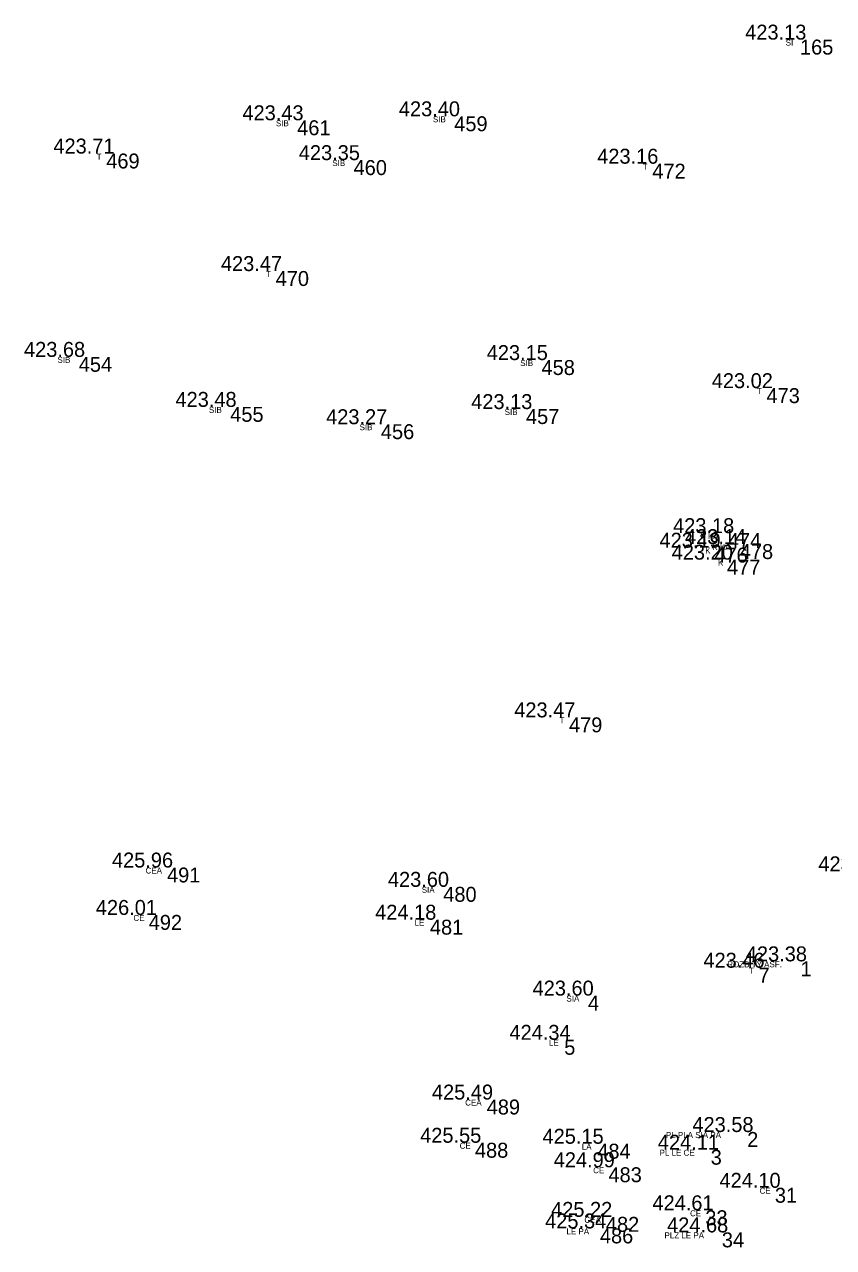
# Model space of a CAD drawing. Extents: x -639373 to -639057, y -1138651 to -1138359.
# Drawn here: x -639183 to -639142.4, y -1138650.6 to -1138589.2 of the extents above; entities that cross this region are included whole.
import ezdxf

# ---------------------------------------------------------------- set-up
doc = ezdxf.new("R2010")
doc.units = 0
for name, color, linetype in [('Vrstva 11', 7, 'Continuous'), ('Vrstva 12', 7, 'Continuous'), ('Vrstva 13', 7, 'Continuous'), ('Vrstva 14', 7, 'Continuous'), ('Vrstva 57', 7, 'Continuous')]:
    doc.layers.add(name, color=color, linetype=linetype)

msp = doc.modelspace()

# ---------------------------------------------------------------- linework, layer by layer
at = {"layer": 'Vrstva 11'}
for p, q in [((-639144.39, -1138589.97), (-639144.39, -1138589.97)), ((-639169.62, -1138594.02), (-639169.62, -1138594.02)), ((-639161.74, -1138593.82), (-639161.74, -1138593.82)), ((-639179.2, -1138595.69), (-639179.2, -1138595.69)), ((-639166.79, -1138596.02), (-639166.79, -1138596.02)), ((-639151.8, -1138596.2), (-639151.8, -1138596.2)), ((-639170.7, -1138601.59), (-639170.7, -1138601.59)), ((-639180.58, -1138605.9), (-639180.58, -1138605.9)), ((-639157.36, -1138606.06), (-639157.36, -1138606.06)), ((-639146.07, -1138607.47), (-639146.07, -1138607.47)), ((-639172.98, -1138608.41), (-639172.98, -1138608.41)), ((-639158.14, -1138608.52), (-639158.14, -1138608.52)), ((-639165.42, -1138609.28), (-639165.42, -1138609.28)), ((-639148.01, -1138614.75), (-639148.01, -1138614.75)), ((-639148.69, -1138615.48), (-639148.69, -1138615.48)), ((-639147.41, -1138615.3), (-639147.41, -1138615.3)), ((-639148.05, -1138616.08), (-639148.05, -1138616.08)), ((-639155.98, -1138624), (-639155.98, -1138624)), ((-639176.15, -1138631.54), (-639176.15, -1138631.54)), ((-639162.29, -1138632.51), (-639162.29, -1138632.51)), ((-639177.07, -1138633.92), (-639177.07, -1138633.92)), ((-639162.96, -1138634.16), (-639162.96, -1138634.16)), ((-639146.47, -1138636.57), (-639146.47, -1138636.57)), ((-639144.36, -1138636.25), (-639144.36, -1138636.25)), ((-639155.03, -1138637.97), (-639155.03, -1138637.97)), ((-639156.22, -1138640.19), (-639156.22, -1138640.19)), ((-639160.11, -1138643.19), (-639160.11, -1138643.19)), ((-639147.04, -1138644.82), (-639147.04, -1138644.82)), ((-639160.7, -1138645.36), (-639160.7, -1138645.36)), ((-639154.56, -1138645.41), (-639154.56, -1138645.41)), ((-639148.87, -1138645.71), (-639148.87, -1138645.71)), ((-639154, -1138646.59), (-639154, -1138646.59)), ((-639145.65, -1138647.62), (-639145.65, -1138647.62)), ((-639149.14, -1138648.75), (-639149.14, -1138648.75)), ((-639154.13, -1138649.08), (-639154.13, -1138649.08)), ((-639154.43, -1138649.66), (-639154.43, -1138649.66)), ((-639148.31, -1138649.86), (-639148.31, -1138649.86))]:
    msp.add_line(p, q, dxfattribs=at)

# ---------------------------------------------------------------- texts
at = {"layer": 'Vrstva 12'}
for s, p in [('425.96 ', (-639178.636, -1138631.54)), ('423.60 ', (-639164.789, -1138632.51)), ('426.01 ', (-639179.445, -1138633.92)), ('424.18 ', (-639165.429, -1138634.16)), ('423.60 ', (-639157.529, -1138637.97)), ('424.34 ', (-639158.689, -1138640.19)), ('425.49 ', (-639162.579, -1138643.19)), ('425.55 ', (-639163.17, -1138645.36)), ('423.58 ', (-639149.509, -1138644.82)), ('425.15 ', (-639157.03, -1138645.41)), ('424.11 ', (-639151.245, -1138645.71)), ('424.99 ', (-639156.469, -1138646.59)), ('424.10 ', (-639148.149, -1138647.62)), ('424.61 ', (-639151.515, -1138648.75)), ('425.34 ', (-639156.899, -1138649.66)), ('425.22 ', (-639156.599, -1138649.08)), ('424.68 ', (-639150.779, -1138649.86))]:
    msp.add_text(s, height=0.75, dxfattribs=at).set_placement(p)
at = {"layer": 'Vrstva 13'}
for s, p in [(' 165', (-639144.39, -1138590.72)), (' 461', (-639169.62, -1138594.77)), (' 459', (-639161.74, -1138594.57)), (' 469', (-639179.2, -1138596.44)), (' 460', (-639166.79, -1138596.77)), (' 472', (-639151.8, -1138596.95)), (' 470', (-639170.7, -1138602.34)), (' 454', (-639180.58, -1138606.65)), (' 458', (-639157.36, -1138606.81)), (' 473', (-639146.07, -1138608.22)), (' 455', (-639172.98, -1138609.16)), (' 457', (-639158.14, -1138609.27)), (' 456', (-639165.42, -1138610.03)), (' 474', (-639148.01, -1138615.5)), (' 476', (-639148.69, -1138616.23)), (' 478', (-639147.41, -1138616.05)), (' 477', (-639148.05, -1138616.83)), (' 479', (-639155.98, -1138624.75)), (' 491', (-639176.15, -1138632.29)), (' 480', (-639162.29, -1138633.26)), (' 492', (-639177.07, -1138634.67)), (' 481', (-639162.96, -1138634.91)), (' 7', (-639146.47, -1138637.32)), (' 1', (-639144.36, -1138637)), (' 4', (-639155.03, -1138638.72)), (' 5', (-639156.22, -1138640.94)), (' 489', (-639160.11, -1138643.94)), (' 2', (-639147.04, -1138645.57)), (' 488', (-639160.7, -1138646.11)), (' 484', (-639154.56, -1138646.16)), (' 3', (-639148.87, -1138646.46)), (' 483', (-639154, -1138647.34)), (' 31', (-639145.65, -1138648.37)), (' 33', (-639149.14, -1138649.5)), (' 482', (-639154.13, -1138649.83)), (' 486', (-639154.43, -1138650.41)), (' 34', (-639148.31, -1138650.61))]:
    msp.add_text(s, height=0.75, dxfattribs=at).set_placement(p)
at = {"layer": 'Vrstva 14'}
for s, p in [('423.13 ', (-639146.859, -1138589.97)), ('423.43 ', (-639172.089, -1138594.02)), ('423.40 ', (-639164.239, -1138593.82)), ('423.71 ', (-639181.575, -1138595.69)), ('423.35 ', (-639169.26, -1138596.02)), ('423.16 ', (-639154.286, -1138596.2)), ('423.47 ', (-639173.169, -1138601.59)), ('423.68 ', (-639183.049, -1138605.9)), ('423.15 ', (-639159.83, -1138606.06)), ('423.02 ', (-639148.539, -1138607.47)), ('423.48 ', (-639175.449, -1138608.41)), ('423.13 ', (-639160.609, -1138608.52)), ('423.27 ', (-639167.889, -1138609.28)), ('423.18 ', (-639150.479, -1138614.75)), ('423.19 ', (-639151.159, -1138615.48)), ('423.14 ', (-639149.879, -1138615.3)), ('423.20 ', (-639150.549, -1138616.08)), ('423.47 ', (-639158.449, -1138624)), ('423.23 ', (-639143.189, -1138631.73)), ('423.46 ', (-639148.956, -1138636.57)), ('423.38 ', (-639146.829, -1138636.25))]:
    msp.add_text(s, height=0.75, dxfattribs=at).set_placement(p)
at = {"layer": 'Vrstva 57'}
for s, p in [('SI', (-639144.828, -1138590.27)), ('SIB', (-639170.409, -1138594.32)), ('SIB', (-639162.529, -1138594.12)), ('T', (-639179.4, -1138595.99)), ('SIB', (-639167.579, -1138596.32)), ('T', (-639152, -1138596.5)), ('T', (-639170.9, -1138601.89)), ('SIB', (-639181.369, -1138606.2)), ('SIB', (-639158.149, -1138606.36)), ('T', (-639146.27, -1138607.77)), ('SIB', (-639173.769, -1138608.71)), ('SIB', (-639158.929, -1138608.82)), ('SIB', (-639166.209, -1138609.58)), ('K KA', (-639149.11, -1138615.05)), ('K', (-639148.865, -1138615.78)), ('K KA', (-639148.51, -1138615.6)), ('K', (-639148.225, -1138616.38)), ('T', (-639156.18, -1138624.3)), ('CEA', (-639176.95, -1138631.84)), ('SIA', (-639163.09, -1138632.81)), ('CE', (-639177.557, -1138634.22)), ('LE', (-639163.448, -1138634.46)), ('ROZBITY ASF.', (-639147.759, -1138636.55)), ('T', (-639146.67, -1138636.87)), ('SIA', (-639155.83, -1138638.27)), ('LE', (-639156.708, -1138640.49)), ('CEA', (-639160.91, -1138643.49)), ('PL PLA SIA PA', (-639150.84, -1138645.12)), ('CE', (-639161.188, -1138645.66)), ('LA', (-639155.06, -1138645.71)), ('PL LE CE', (-639151.157, -1138646.01)), ('CE', (-639154.488, -1138646.89)), ('CE', (-639146.138, -1138647.92)), ('CE', (-639149.628, -1138649.05)), ('CEA', (-639154.93, -1138649.38)), ('LE PA', (-639155.83, -1138649.96)), ('PLZ LE PA', (-639150.91, -1138650.16))]:
    msp.add_text(s, height=0.3, dxfattribs=at).set_placement(p)

doc.saveas('drawing.dxf')
